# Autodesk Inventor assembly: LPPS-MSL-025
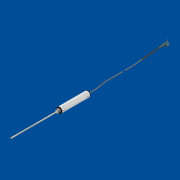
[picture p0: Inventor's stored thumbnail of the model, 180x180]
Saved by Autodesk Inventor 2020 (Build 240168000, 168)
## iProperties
Created: 2019-07
Part Number: LPPS-MSL-025
Document SubType Name: Assembly
Designer: J. Nielson
Author: J. Nielson
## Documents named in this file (5)
- D:\Users\Justin\Documents\CAD Drawings\The Sensor Connection\LPPS\LPPS-MSL\3D\LPPS-MSL-075\LPPS-MSL-075.iam
- D:\Users\Justin\Documents\CAD Drawings\The Sensor Connection\LPPS\LPPS-MSL\3D\MSL PARTS\ISO 4035 - M8BS EN.ipt
- D:\Users\Justin\Documents\CAD Drawings\The Sensor Connection\LPPS\LPPS-MSL\3D\LPPS-MSL-075\LPPS-MSL-075 HOUSING_SW.ipt
- D:\Users\Justin\Documents\CAD Drawings\The Sensor Connection\LPPS\LPPS-MSL\3D\LPPS-MSL-075\LPPS-MSL-075 SHAFT_SW.ipt
- D:\Users\Justin\Documents\CAD Drawings\The Sensor Connection\LPPS\LPPS-MSL\3D\LPPS-MSL-075\LPPS-MSL-075 Spring.ipt
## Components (4 placed, 4 different names)
1. LPPS-MSL-075 HOUSING_SW:1 — Mate:1, Mate:2, Mate:3, Flush:1
2. LPPS-MSL-075 SHAFT_SW:1 — Mate:1, Mate:2, Angle:2
3. ISO 4035 - M8BS EN:1 — Mate:3, Angle:1, Flush:1
4. LPPS-MSL-075 Spring:1 — Flush:2
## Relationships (7: Mate 3, Angle 2, Flush 2)
- Mate:1: LPPS-MSL-075 HOUSING_SW:1 ↔ LPPS-MSL-075 SHAFT_SW:1
- Mate:2: LPPS-MSL-075 HOUSING_SW:1 ↔ LPPS-MSL-075 SHAFT_SW:1
- Mate:3: LPPS-MSL-075 HOUSING_SW:1 ↔ ISO 4035 - M8BS EN:1
- Angle:1: ISO 4035 - M8BS EN:1
- Flush:1: LPPS-MSL-075 HOUSING_SW:1 ↔ ISO 4035 - M8BS EN:1
- Flush:2: LPPS-MSL-075 Spring:1
- Angle:2: LPPS-MSL-075 SHAFT_SW:1
